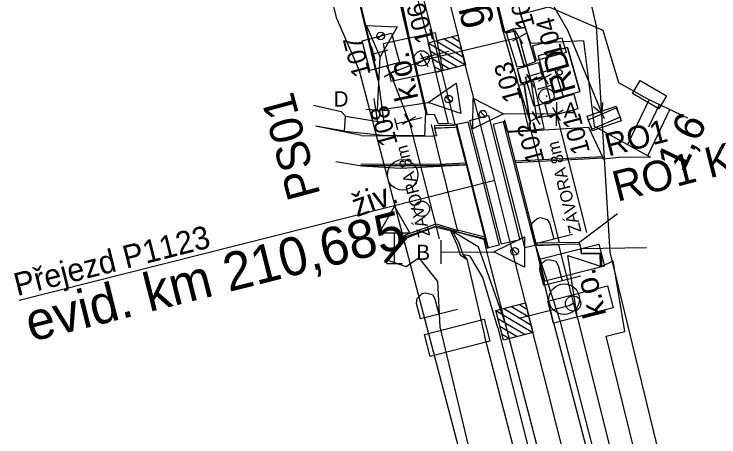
# Model space of a CAD drawing. Extents: x -754679 to -754173, y -1169241 to -1168288.
# Drawn here: x -754417.2 to -754371, y -1168972.24 to -1168944.54 of the extents above; entities that cross this region are included whole.
import ezdxf

# ---------------------------------------------------------------- set-up
doc = ezdxf.new("R2010")
doc.units = 0
for name, color, linetype in [('Vrstva 1', 7, 'Continuous'), ('Vrstva 13', 7, 'Continuous'), ('Vrstva 16', 7, 'Continuous'), ('Vrstva 23', 7, 'Continuous'), ('Vrstva 25', 7, 'Continuous'), ('Vrstva 27', 7, 'Continuous'), ('Vrstva 3', 7, 'Continuous'), ('Vrstva 31', 7, 'Continuous'), ('Vrstva 33', 7, 'Continuous'), ('Vrstva 37', 7, 'Continuous'), ('Vrstva 4', 7, 'Continuous'), ('Vrstva 43', 7, 'Continuous'), ('Vrstva 45', 7, 'Continuous'), ('Vrstva 48', 7, 'Continuous'), ('Vrstva 49', 7, 'Continuous'), ('Vrstva 51', 7, 'Continuous'), ('Vrstva 53', 7, 'Continuous'), ('Vrstva 59', 7, 'Continuous'), ('Vrstva 6', 7, 'Continuous'), ('Vrstva 60', 7, 'Continuous'), ('Vrstva 7', 7, 'Continuous')]:
    doc.layers.add(name, color=color, linetype=linetype)

msp = doc.modelspace()

# ---------------------------------------------------------------- linework, layer by layer
at = {"layer": 'Vrstva 1'}
for p, q in [((-754391.329, -1168951.517), (-754389.349, -1168959.268)), ((-754381.637, -1168951.088), (-754379.683, -1168958.846))]:
    msp.add_line(p, q, dxfattribs=at)
for points in [[(-754384.656, -1168959.571), (-754385.936, -1168954.491), (-754386.734, -1168951.322), (-754387.865, -1168946.893), (-754387.928, -1168946.598), (-754389.016, -1168942.293), (-754391.2, -1168933.67), (-754393.647, -1168923.979), (-754396.084, -1168914.315), (-754398.294, -1168905.574)], [(-754382.327, -1168968.778), (-754383.436, -1168964.432), (-754383.656, -1168963.522), (-754384.656, -1168959.571)], [(-754371.756, -1169010.617), (-754373.805, -1169002.503), (-754376.012, -1168993.767), (-754377.617, -1168987.413), (-754379.98, -1168978.062), (-754382.327, -1168968.778)]]:
    msp.add_lwpolyline(points, dxfattribs=at)
at = {"layer": 'Vrstva 13'}
for p, q in [((-754385.032, -1168945.69), (-754385.963, -1168941.8)), ((-754384.759, -1168941.493), (-754384.006, -1168944.538)), ((-754385.064, -1168945.684), (-754386.023, -1168941.847)), ((-754385.032, -1168945.69), (-754384.522, -1168945.516)), ((-754385.064, -1168945.684), (-754385.032, -1168945.69)), ((-754375.751, -1168959.859), (-754380.036, -1168959.915)), ((-754380.025, -1168960.213), (-754378.726, -1168960.213)), ((-754378.753, -1168961.045), (-754378.786, -1168960.228)), ((-754378.726, -1168960.213), (-754378.701, -1168961.079)), ((-754378.701, -1168961.079), (-754378.753, -1168961.045))]:
    msp.add_line(p, q, dxfattribs=at)
for points in [[(-754384.006, -1168944.538), (-754383.71, -1168945.407), (-754384.522, -1168945.516)], [(-754385.064, -1168945.684), (-754384.955, -1168945.759), (-754384.522, -1168945.516)], [(-754378.726, -1168960.213), (-754378.786, -1168960.228), (-754380.038, -1168960.207), (-754380.043, -1168959.901), (-754380.036, -1168959.915)], [(-754380.036, -1168959.915), (-754380.025, -1168960.213), (-754380.038, -1168960.207)]]:
    msp.add_lwpolyline(points, dxfattribs=at)
at = {"layer": 'Vrstva 16'}
for p, q in [((-754390.209, -1168950.962), (-754395.222, -1168929.578)), ((-754397.82, -1168929.888), (-754393.322, -1168948.872)), ((-754384.955, -1168945.759), (-754384.428, -1168945.654)), ((-754384.428, -1168945.654), (-754383.763, -1168947.919)), ((-754395.546, -1168952.201), (-754395.477, -1168951.215)), ((-754391.51, -1168961.104), (-754392.688, -1168960.67)), ((-754377.17, -1168965.333), (-754377.937, -1168960.698)), ((-754380.262, -1168964.46), (-754374.593, -1168987.21)), ((-754383.092, -1168990.79), (-754389.273, -1168965.032)), ((-754378.402, -1168965.63), (-754377.17, -1168965.333)), ((-754380.395, -1168988.747), (-754386.358, -1168965.597)), ((-754373.145, -1168986.727), (-754378.402, -1168965.63))]:
    msp.add_line(p, q, dxfattribs=at)
for points in [[(-754384.955, -1168945.759), (-754384.237, -1168947.982), (-754383.763, -1168947.919)], [(-754395.477, -1168951.215), (-754392.947, -1168951.633), (-754393.322, -1168948.872)], [(-754383.768, -1168949.156), (-754384.136, -1168949.206), (-754383.375, -1168951.611), (-754383.768, -1168949.156)], [(-754395.546, -1168952.201), (-754393.01, -1168952.466), (-754390.289, -1168952.493), (-754390.209, -1168950.962)], [(-754392.688, -1168960.67), (-754391.408, -1168959.175), (-754389.621, -1168958.478), (-754388.593, -1168958.711), (-754388.173, -1168959.62), (-754387.958, -1168960.306), (-754387.518, -1168960.602), (-754386.358, -1168965.597)], [(-754389.273, -1168965.032), (-754389.425, -1168962.053), (-754390.641, -1168960.512), (-754391.51, -1168961.104)], [(-754380.262, -1168964.46), (-754380.906, -1168960.36), (-754378.753, -1168961.045), (-754378.701, -1168961.079), (-754377.937, -1168960.698)]]:
    msp.add_lwpolyline(points, dxfattribs=at)
at = {"layer": 'Vrstva 23'}
for p, q in [((-754380.917, -1168946.723), (-754382.852, -1168947.261)), ((-754380.917, -1168946.723), (-754380.127, -1168949.604)), ((-754382.852, -1168947.261), (-754382.062, -1168950.142)), ((-754384.221, -1168948.119), (-754382.823, -1168947.697)), ((-754382.062, -1168950.142), (-754380.127, -1168949.604))]:
    msp.add_line(p, q, dxfattribs=at)
for points in [[(-754393.344, -1168948.888), (-754397.546, -1168931.205), (-754401.742, -1168913.695), (-754408.583, -1168884.482)], [(-754382.852, -1168947.261), (-754382.062, -1168950.142), (-754380.127, -1168949.604), (-754380.917, -1168946.723), (-754382.852, -1168947.261)], [(-754382.823, -1168947.697), (-754382.557, -1168948.653), (-754383.948, -1168949.058), (-754383.977, -1168949.056), (-754384.212, -1168948.093), (-754384.221, -1168948.119), (-754383.948, -1168949.058)]]:
    msp.add_lwpolyline(points, dxfattribs=at)
at = {"layer": 'Vrstva 25'}
for points in [[(-754385.337, -1168937.932), (-754380.924, -1168945.594), (-754378.67, -1168951.057), (-754378.525, -1168951.376)], [(-754381.29, -1168946.084), (-754381.023, -1168947.048), (-754382.95, -1168947.584), (-754383.217, -1168946.62), (-754381.29, -1168946.084)], [(-754376.658, -1168949.746), (-754376.155, -1168948.882), (-754374.426, -1168949.888), (-754374.929, -1168950.752), (-754376.658, -1168949.746)], [(-754382.167, -1168951.272), (-754382.434, -1168950.308), (-754380.507, -1168949.772), (-754380.24, -1168950.736), (-754382.167, -1168951.272)], [(-754379.308, -1168952.174), (-754379.633, -1168951.228), (-754377.742, -1168950.578), (-754377.417, -1168951.524), (-754379.308, -1168952.174)]]:
    msp.add_lwpolyline(points, dxfattribs=at)
at = {"layer": 'Vrstva 27'}
for p, q in [((-754390.53, -1168947.452), (-754390.434, -1168947.426)), ((-754382.319, -1168949.867), (-754382.295, -1168949.963)), ((-754380.605, -1168963.514), (-754380.511, -1168963.48))]:
    msp.add_line(p, q, dxfattribs=at)
for points in [[(-754390.482, -1168947.439), (-754390.388, -1168947.376), (-754388.713, -1168946.964)], [(-754380.558, -1168963.497), (-754380.816, -1168963.643), (-754384.119, -1168964.483)]]:
    msp.add_lwpolyline(points, dxfattribs=at)
for centre in [(-754390.482, -1168947.439), (-754382.307, -1168949.915), (-754380.558, -1168963.497)]:
    msp.add_circle(centre, 0.5, dxfattribs=at)
at = {"layer": 'Vrstva 3'}
for p, q in [((-754390.05, -1168946.419), (-754387.618, -1168947.862)), ((-754389.537, -1168946.288), (-754387.749, -1168947.348)), ((-754389.022, -1168946.156), (-754387.88, -1168946.834)), ((-754388.509, -1168946.025), (-754388.011, -1168946.32)), ((-754389.919, -1168946.932), (-754388.131, -1168947.993)), ((-754389.788, -1168947.447), (-754388.646, -1168948.124)), ((-754389.657, -1168947.96), (-754389.159, -1168948.256)), ((-754385.621, -1168963.958), (-754383.189, -1168965.401)), ((-754385.108, -1168963.827), (-754383.32, -1168964.887)), ((-754384.593, -1168963.695), (-754383.451, -1168964.373)), ((-754384.08, -1168963.564), (-754383.582, -1168963.859)), ((-754385.49, -1168964.471), (-754383.702, -1168965.532)), ((-754385.359, -1168964.986), (-754384.217, -1168965.663)), ((-754385.228, -1168965.499), (-754384.73, -1168965.794))]:
    msp.add_line(p, q, dxfattribs=at)
for points in [[(-754388.112, -1168945.924), (-754387.618, -1168947.862), (-754389.555, -1168948.357), (-754390.05, -1168946.419)], [(-754383.683, -1168963.463), (-754383.189, -1168965.401), (-754385.127, -1168965.895), (-754385.621, -1168963.958)]]:
    msp.add_lwpolyline(points, close=True, dxfattribs=at)
at = {"layer": 'Vrstva 31'}
msp.add_lwpolyline([(-754388.719, -1168923.201), (-754385.337, -1168937.932), (-754380.924, -1168945.594), (-754378.67, -1168951.057), (-754378.525, -1168951.376)], dxfattribs=at)
at = {"layer": 'Vrstva 33'}
for p, q in [((-754393.523, -1168947.612), (-754393.778, -1168946.645)), ((-754393.65, -1168947.129), (-754392.684, -1168946.873)), ((-754382.106, -1168948.711), (-754381.818, -1168949.669)), ((-754381.962, -1168949.19), (-754382.92, -1168949.478)), ((-754379.573, -1168951.471), (-754379.569, -1168951.463))]:
    msp.add_line(p, q, dxfattribs=at)
for points in [[(-754393.879, -1168948.223), (-754394.389, -1168946.289), (-754392.455, -1168945.779), (-754391.945, -1168947.713), (-754393.879, -1168948.223)], [(-754381.771, -1168948.089), (-754381.196, -1168950.004), (-754383.111, -1168950.579), (-754383.686, -1168948.664), (-754381.771, -1168948.089)], [(-754379.227, -1168950.589), (-754378.657, -1168951.07), (-754378.614, -1168950.326)], [(-754383.287, -1168958.57), (-754383.262, -1168958.238), (-754382.923, -1168957.924), (-754382.708, -1168957.87), (-754382.251, -1168957.983), (-754382.087, -1168958.267)], [(-754382.087, -1168958.267), (-754381.832, -1168959.278)], [(-754383.032, -1168959.581), (-754383.287, -1168958.57)], [(-754380.6, -1168958.968), (-754383.032, -1168959.581)], [(-754382.732, -1168961.313), (-754382.708, -1168960.981), (-754382.368, -1168960.667), (-754382.154, -1168960.613), (-754381.697, -1168960.726), (-754381.532, -1168961.01)], [(-754381.532, -1168961.01), (-754381.277, -1168962.021)], [(-754382.477, -1168962.324), (-754382.732, -1168961.313)], [(-754380.045, -1168961.71), (-754382.477, -1168962.324)], [(-754390.816, -1168963.496), (-754390.792, -1168963.164), (-754390.452, -1168962.85), (-754390.238, -1168962.796), (-754389.781, -1168962.909), (-754389.616, -1168963.193)], [(-754390.561, -1168964.507), (-754390.816, -1168963.496)], [(-754389.616, -1168963.193), (-754389.361, -1168964.204)], [(-754388.129, -1168963.893), (-754390.561, -1168964.507)]]:
    msp.add_lwpolyline(points, dxfattribs=at)
for points in [[(-754379.575, -1168951.465), (-754377.738, -1168950.674), (-754377.475, -1168951.287), (-754379.312, -1168952.078)], [(-754382.404, -1168962.035), (-754382.768, -1168960.591), (-754378.861, -1168959.607), (-754378.498, -1168961.051)], [(-754381.848, -1168964.778), (-754382.212, -1168963.334), (-754378.306, -1168962.348), (-754377.941, -1168963.791)], [(-754389.932, -1168966.961), (-754390.296, -1168965.517), (-754386.39, -1168964.531), (-754386.025, -1168965.974)]]:
    msp.add_lwpolyline(points, close=True, dxfattribs=at)
at = {"layer": 'Vrstva 37'}
msp.add_circle((-754390.471, -1168957.291), 0.5, dxfattribs=at)
at = {"layer": 'Vrstva 4'}
for p, q in [((-754395.222, -1168929.578), (-754390.121, -1168951.135)), ((-754394.179, -1168929.708), (-754388.744, -1168951.72)), ((-754388.295, -1168951.767), (-754393.809, -1168929.698)), ((-754385.154, -1168945.699), (-754386.014, -1168941.847)), ((-754393.356, -1168946.129), (-754392.992, -1168945.803)), ((-754385.154, -1168945.699), (-754384.183, -1168949.051)), ((-754393.613, -1168950.071), (-754393.391, -1168951.611)), ((-754388.912, -1168949.959), (-754388.521, -1168950.254)), ((-754381.644, -1168951.866), (-754381.63, -1168950.31)), ((-754394.153, -1168950.763), (-754392.599, -1168950.843)), ((-754386.308, -1168951.266), (-754386.649, -1168950.915)), ((-754392.265, -1168951.347), (-754392.081, -1168952.103)), ((-754388.744, -1168951.72), (-754389.386, -1168951.727)), ((-754388.295, -1168951.767), (-754388.744, -1168951.72)), ((-754388.251, -1168951.769), (-754388.18, -1168951.751)), ((-754385.695, -1168955.447), (-754416.868, -1168963.298)), ((-754386.398, -1168959.295), (-754388.488, -1168958.734)), ((-754388.488, -1168958.734), (-754388.043, -1168959.526)), ((-754389.229, -1168959.347), (-754389.231, -1168960.903)), ((-754388.043, -1168959.526), (-754387.779, -1168960.28)), ((-754383.049, -1168959.681), (-754382.957, -1168959.657)), ((-754381.503, -1168959.659), (-754382.994, -1168959.713)), ((-754381.376, -1168964.701), (-754382.994, -1168959.713)), ((-754381.816, -1168964.835), (-754382.994, -1168959.713)), ((-754380.262, -1168964.46), (-754381.503, -1168959.659)), ((-754386.178, -1168959.871), (-754386.113, -1168959.854)), ((-754384.561, -1168959.911), (-754384.217, -1168960.259)), ((-754384.968, -1168964.915), (-754385.997, -1168960.947)), ((-754385.501, -1168965.091), (-754386.471, -1168961.789)), ((-754380.262, -1168964.46), (-754374.593, -1168987.21)), ((-754378.902, -1168988.336), (-754384.968, -1168964.915)), ((-754381.816, -1168964.835), (-754375.862, -1168987.584)), ((-754375.554, -1168987.357), (-754381.376, -1168964.701)), ((-754385.501, -1168965.091), (-754379.508, -1168988.473)), ((-754380.395, -1168988.747), (-754386.358, -1168965.597))]:
    msp.add_line(p, q, dxfattribs=at)
for points in [[(-754393.376, -1168950.803), (-754393.209, -1168947.33), (-754394.098, -1168945.279), (-754392.102, -1168945.369), (-754393.209, -1168947.33)], [(-754383.71, -1168945.407), (-754383.049, -1168947.673), (-754383.763, -1168947.919), (-754384.428, -1168945.654), (-754384.522, -1168945.516), (-754383.71, -1168945.407)], [(-754393.502, -1168950.841), (-754390.062, -1168950.335), (-754388.221, -1168949.067), (-754387.924, -1168951.043), (-754390.062, -1168950.335)], [(-754384.183, -1168949.051), (-754383.468, -1168952.159), (-754384.853, -1168952.232), (-754385.049, -1168951.469)], [(-754383.468, -1168952.159), (-754382.456, -1168952.028), (-754383.132, -1168948.942), (-754383.948, -1168949.058), (-754383.768, -1168949.156), (-754383.375, -1168951.611), (-754383.468, -1168952.159)], [(-754381.637, -1168951.088), (-754385.114, -1168951.068), (-754387.126, -1168952.042), (-754387.12, -1168950.044), (-754385.114, -1168951.068)], [(-754392.173, -1168951.725), (-754390.485, -1168951.309), (-754390.485, -1168951.309)], [(-754389.386, -1168951.727), (-754389.648, -1168951.116), (-754390.121, -1168951.135)], [(-754384.042, -1168959.317), (-754385.257, -1168959.617), (-754387.319, -1168951.515), (-754386.094, -1168951.188), (-754384.042, -1168959.317)], [(-754388.251, -1168951.769), (-754388.199, -1168951.972), (-754387.569, -1168954.421), (-754386.369, -1168959.123), (-754386.343, -1168959.225), (-754386.338, -1168959.246), (-754386.178, -1168959.871)], [(-754385.407, -1168959.668), (-754386.113, -1168959.854), (-754388.18, -1168951.751), (-754387.468, -1168951.586), (-754385.407, -1168959.668)], [(-754383.749, -1168959.835), (-754383.049, -1168959.681), (-754385.116, -1168951.584), (-754385.803, -1168951.759), (-754385.802, -1168951.762), (-754383.749, -1168959.835)], [(-754385.02, -1168951.56), (-754385.116, -1168951.584)], [(-754382.957, -1168959.657), (-754385.02, -1168951.56)], [(-754388.488, -1168958.734), (-754386.775, -1168959.754), (-754384.968, -1168964.915)], [(-754389.23, -1168960.125), (-754385.753, -1168960.118), (-754383.749, -1168959.127), (-754383.739, -1168961.125), (-754385.753, -1168960.118)], [(-754385.997, -1168960.947), (-754386.261, -1168959.886), (-754386.398, -1168959.295)], [(-754386.471, -1168961.789), (-754387.297, -1168960.39), (-754387.779, -1168960.28)], [(-754387.779, -1168960.28), (-754387.518, -1168960.602), (-754386.358, -1168965.597)]]:
    msp.add_lwpolyline(points, dxfattribs=at)
for centre in [(-754393.174, -1168945.967), (-754388.718, -1168950.107), (-754386.477, -1168951.09), (-754384.39, -1168960.085)]:
    msp.add_circle(centre, 0.248, dxfattribs=at)
at = {"layer": 'Vrstva 43'}
for p, q in [((-754388.13, -1168958.682), (-754389.832, -1168951.766)), ((-754381.456, -1168959.502), (-754383.446, -1168951.67))]:
    msp.add_line(p, q, dxfattribs=at)
for centre in [(-754391.734, -1168955.072), (-754381.14, -1168963.213)]:
    msp.add_circle(centre, 1, dxfattribs=at)
at = {"layer": 'Vrstva 45'}
for points in [[(-754391.329, -1168951.517), (-754392.52, -1168948.41), (-754390.32, -1168947.54), (-754384.1, -1168946.05), (-754383.34, -1168948.91)], [(-754382.42, -1168948.71), (-754383.34, -1168948.91)], [(-754383.34, -1168948.91), (-754382.96, -1168951.34), (-754381.637, -1168951.088)]]:
    msp.add_lwpolyline(points, dxfattribs=at)
at = {"layer": 'Vrstva 48'}
for p, q in [((-754375.576, -1168950.125), (-754376.982, -1168953.083)), ((-754374.899, -1168950.446), (-754375.611, -1168951.946)), ((-754374.221, -1168950.768), (-754375.666, -1168953.808))]:
    msp.add_line(p, q, dxfattribs=at)
at = {"layer": 'Vrstva 49'}
for points in [[(-754384.006, -1168944.538), (-754382.158, -1168944.067), (-754378.6, -1168945.58), (-754377.58, -1168949.01), (-754375.672, -1168950.079), (-754373.052, -1168951.324)], [(-754379.885, -1168946.291), (-754383.334, -1168946.469), (-754383.71, -1168945.407), (-754384.006, -1168944.538)], [(-754379.885, -1168946.291), (-754379.174, -1168951.877), (-754375.483, -1168953.908)], [(-754397.582, -1168950.504), (-754395.757, -1168950.913), (-754395.477, -1168951.215)], [(-754395.546, -1168952.201), (-754397.45, -1168951.868)]]:
    msp.add_lwpolyline(points, dxfattribs=at)
at = {"layer": 'Vrstva 51'}
for p, q in [((-754388.305, -1168951.83), (-754389.651, -1168951.864)), ((-754388.26, -1168951.97), (-754389.641, -1168952.015)), ((-754394.422, -1168952.497), (-754389.758, -1168952.527)), ((-754377.567, -1168953.938), (-754378.597, -1168954.036)), ((-754394.492, -1168954.446), (-754389.242, -1168954.445)), ((-754394.471, -1168954.337), (-754389.288, -1168954.378)), ((-754389.254, -1168954.492), (-754388.995, -1168954.482)), ((-754388.995, -1168954.482), (-754387.569, -1168954.421)), ((-754380.13, -1168959.479), (-754377.659, -1168957.604)), ((-754389.542, -1168958.287), (-754388.252, -1168958.676)), ((-754389.488, -1168958.402), (-754387.963, -1168958.835)), ((-754382.989, -1168959.532), (-754380.13, -1168959.479)), ((-754392.763, -1168960.875), (-754391.763, -1168960.875))]:
    msp.add_line(p, q, dxfattribs=at)
for points in [[(-754394.422, -1168952.497), (-754397.45, -1168951.868)], [(-754389.651, -1168951.864), (-754389.641, -1168952.008), (-754389.641, -1168952.015), (-754389.509, -1168952.517), (-754389.758, -1168952.527)], [(-754389.641, -1168952.008), (-754389.633, -1168952.008), (-754388.281, -1168951.95)], [(-754378.633, -1168953.874), (-754379.525, -1168951.969), (-754383.21, -1168952.179), (-754383.477, -1168952.204), (-754384.839, -1168952.296)], [(-754396.105, -1168954.199), (-754394.412, -1168954.467)], [(-754389.288, -1168954.378), (-754387.625, -1168954.272), (-754387.608, -1168954.271)], [(-754384.382, -1168954.15), (-754378.633, -1168953.874), (-754378.608, -1168953.978)], [(-754378.597, -1168954.036), (-754378.608, -1168953.978), (-754384.364, -1168954.276)], [(-754375.483, -1168953.908), (-754377.567, -1168953.938)], [(-754394.412, -1168954.467), (-754391.899, -1168954.63), (-754389.254, -1168954.492)], [(-754387.571, -1168954.415), (-754387.591, -1168954.415), (-754389.242, -1168954.445)], [(-754392.263, -1168960.875), (-754392.263, -1168958.875), (-754391.263, -1168958.875), (-754392.263, -1168957.125), (-754393.263, -1168958.875), (-754392.263, -1168958.875)], [(-754392.928, -1168960.766), (-754391.546, -1168959.003), (-754389.542, -1168958.287)], [(-754392.821, -1168960.856), (-754391.495, -1168959.096), (-754389.488, -1168958.402)], [(-754388.252, -1168958.676), (-754388.13, -1168958.682), (-754388.047, -1168958.683)], [(-754388.047, -1168958.683), (-754386.411, -1168959.112), (-754386.369, -1168959.123)], [(-754387.963, -1168958.835), (-754386.358, -1168959.241), (-754386.338, -1168959.246)], [(-754392.891, -1168960.815), (-754391.532, -1168959.012), (-754391.546, -1168959.003)], [(-754382.96, -1168959.646), (-754382.937, -1168959.645), (-754380.136, -1168959.582), (-754380.13, -1168959.479)], [(-754380.136, -1168959.582), (-754380.043, -1168959.901)]]:
    msp.add_lwpolyline(points, dxfattribs=at)
at = {"layer": 'Vrstva 53'}
for p, q in [((-754396.56, -1168868.29), (-754379.05, -1168945.33)), ((-754396.05, -1168944.82), (-754406.43, -1168903.09)), ((-754394.57, -1168948.26), (-754396.05, -1168944.82)), ((-754379.05, -1168945.33), (-754378.16, -1168960.13)), ((-754378.16, -1168960.13), (-754373.54, -1168979.01))]:
    msp.add_line(p, q, dxfattribs=at)
msp.add_lwpolyline([(-754345.91, -1169130.8), (-754386.06, -1168980.52), (-754394.57, -1168948.26)], dxfattribs=at)
at = {"layer": 'Vrstva 59'}
msp.add_circle((-754381.446, -1168948.347), 0.175, dxfattribs=at)
at = {"layer": 'Vrstva 6'}
for p, q in [((-754383.667, -1168945.8), (-754384.533, -1168946.3)), ((-754383.85, -1168946.483), (-754384.35, -1168945.617)), ((-754389.887, -1168947.29), (-754390.753, -1168947.79)), ((-754390.07, -1168947.973), (-754390.57, -1168947.107)), ((-754392.087, -1168948.16), (-754392.953, -1168948.66)), ((-754392.27, -1168948.843), (-754392.77, -1168947.977)), ((-754382.17, -1168949.143), (-754382.67, -1168948.277)), ((-754382.907, -1168948.66), (-754383.773, -1168949.16)), ((-754383.09, -1168949.343), (-754383.59, -1168948.477)), ((-754381.987, -1168948.46), (-754382.853, -1168948.96)), ((-754382.71, -1168951.773), (-754383.21, -1168950.907)), ((-754381.204, -1168950.838), (-754382.07, -1168951.338)), ((-754381.387, -1168951.521), (-754381.887, -1168950.655)), ((-754390.896, -1168951.267), (-754391.762, -1168951.767)), ((-754391.079, -1168951.95), (-754391.579, -1168951.084)), ((-754382.527, -1168951.09), (-754383.393, -1168951.59))]:
    msp.add_line(p, q, dxfattribs=at)
at = {"layer": 'Vrstva 7'}
msp.add_lwpolyline([(-754391.909, -1168943.185), (-754391.296, -1168946.122), (-754393.009, -1168946.479), (-754392.499, -1168948.927), (-754389.072, -1168948.212), (-754389.583, -1168945.764), (-754391.296, -1168946.122)], dxfattribs=at)

# ---------------------------------------------------------------- texts
at = {"layer": 'Vrstva 13'}
msp.add_text('gabion', height=2, rotation=103.4595, dxfattribs=at).set_placement((-754386.254, -1168945.261))
at = {"layer": 'Vrstva 23'}
msp.add_text('RD', height=1.5, rotation=105.7615, dxfattribs=at).set_placement((-754380.375, -1168949.515))
at = {"layer": 'Vrstva 25'}
msp.add_text('RO1', height=1.5, rotation=14.2781, dxfattribs=at).set_placement((-754378.247, -1168953.868))
at = {"layer": 'Vrstva 27'}
for rotation, p in [(102.055, (-754390.696, -1168950.059)), (104.2033, (-754378.367, -1168964.226))]:
    msp.add_text('k.o.', height=1.5, rotation=rotation, dxfattribs=at).set_placement(p)
at = {"layer": 'Vrstva 3'}
msp.add_text('PS01', height=2.16, rotation=105, dxfattribs=at).set_placement((-754397.11, -1168956.359))
at = {"layer": 'Vrstva 33'}
msp.add_text('RO1 KS1 KF1', height=2, rotation=14.2781, dxfattribs=at).set_placement((-754377.672, -1168956.84))
at = {"layer": 'Vrstva 4'}
for s, p in [('D', (-754396.249, -1168950.593)), ('A', (-754381.164, -1168951.326)), ('B', (-754390.832, -1168960.645))]:
    msp.add_text(s, height=1, dxfattribs=at).set_placement(p)
for s, height, rotation, p in [('ZÁVORA 8m', 0.8, 104.134, (-754380.004, -1168958.788)), ('ZÁVORA 8m', 0.8, 104.325, (-754389.914, -1168959.045)), ('evid. km 210,685', 2.5, 14.136, (-754416.099, -1168966.015)), ('Přejezd P1123', 1.5, 14.136, (-754416.998, -1168963.018))]:
    msp.add_text(s, height=height, rotation=rotation, dxfattribs=at).set_placement(p)
at = {"layer": 'Vrstva 48'}
msp.add_text('1,6', height=2, rotation=64.5834, dxfattribs=at).set_placement((-754373.34, -1168955.003))
at = {"layer": 'Vrstva 51'}
msp.add_text('živ.', height=1.5, rotation=19.6611, dxfattribs=at).set_placement((-754394.745, -1168957.851))
at = {"layer": 'Vrstva 60'}
for s, p in [('105', (-754383.059, -1168945.298)), ('106', (-754389.659, -1168946.28)), ('104', (-754381.182, -1168947.238)), ('107', (-754393.82, -1168948.479)), ('103', (-754383.914, -1168950.147)), ('108', (-754392.046, -1168953.023)), ('101', (-754379.443, -1168953.554)), ('102', (-754382.43, -1168954.123))]:
    msp.add_text(s, height=1.2, rotation=105, dxfattribs=at).set_placement(p)

doc.saveas('drawing.dxf')
